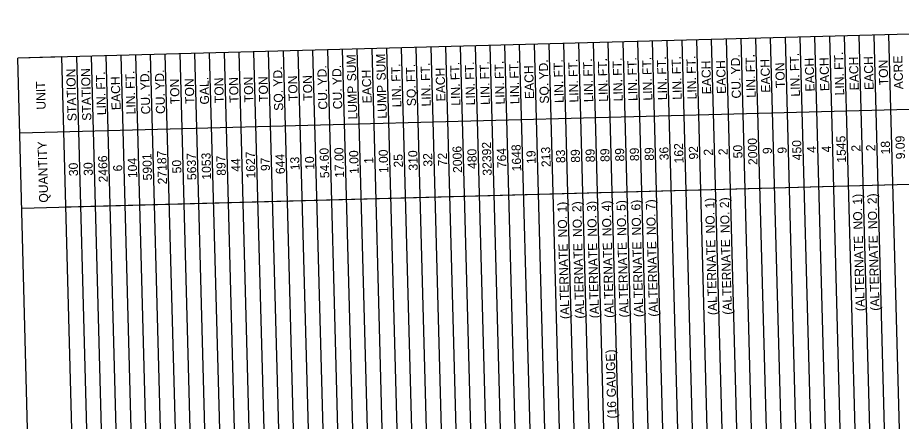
# Model space of a CAD drawing. Extents: x 1930091 to 1931962, y 596452 to 607874.
# Drawn here: x 1930094 to 1930677, y 606818 to 607084 of the extents above; entities that cross this region are included whole.
import ezdxf

# ---------------------------------------------------------------- set-up
doc = ezdxf.new("R2010")
doc.units = 0
doc.layers.add('Default', color=7, linetype='Continuous')

msp = doc.modelspace()

# ---------------------------------------------------------------- linework, layer by layer
at = {"layer": 'Default'}
for p, q in [((1931087.72, 607084.44), (1930093.58, 607057.76)), ((1930481.91, 606398.6), (1930463.95, 607067.7)), ((1930491.66, 606398.86), (1930473.69, 607067.96)), ((1930501.4, 606399.13), (1930483.44, 607068.22)), ((1930511.15, 606399.39), (1930493.19, 607068.48)), ((1930520.9, 606399.65), (1930502.93, 607068.75)), ((1930530.64, 606399.91), (1930512.68, 607069.01)), ((1930540.39, 606400.17), (1930522.43, 607069.27)), ((1930550.14, 606400.43), (1930532.17, 607069.53)), ((1930559.88, 606400.7), (1930541.92, 607069.79)), ((1930569.63, 606400.96), (1930551.67, 607070.05)), ((1930579.37, 606401.22), (1930561.41, 607070.32)), ((1930589.12, 606401.48), (1930571.16, 607070.58)), ((1930598.87, 606401.74), (1930580.91, 607070.84)), ((1930608.61, 606402), (1930590.65, 607071.1)), ((1930618.36, 606402.27), (1930600.4, 607071.36)), ((1930628.11, 606402.53), (1930610.15, 607071.62)), ((1930637.85, 606402.79), (1930619.89, 607071.89)), ((1930647.6, 606403.05), (1930629.64, 607072.15)), ((1930657.35, 606403.31), (1930639.39, 607072.41)), ((1930667.09, 606403.57), (1930649.13, 607072.67)), ((1930676.84, 606403.84), (1930658.88, 607072.93)), ((1930686.59, 606404.1), (1930668.62, 607073.19)), ((1930267.49, 606392.85), (1930249.53, 607061.94)), ((1930277.23, 606393.11), (1930259.27, 607062.21)), ((1930286.98, 606393.37), (1930269.02, 607062.47)), ((1930296.73, 606393.63), (1930278.77, 607062.73)), ((1930306.47, 606393.89), (1930288.51, 607062.99)), ((1930316.22, 606394.16), (1930298.26, 607063.25)), ((1930325.97, 606394.42), (1930308, 607063.51)), ((1930335.71, 606394.68), (1930317.75, 607063.78)), ((1930345.46, 606394.94), (1930327.5, 607064.04)), ((1930355.21, 606395.2), (1930337.24, 607064.3)), ((1930364.95, 606395.46), (1930346.99, 607064.56)), ((1930374.7, 606395.73), (1930356.74, 607064.82)), ((1930384.44, 606395.99), (1930366.48, 607065.08)), ((1930394.19, 606396.25), (1930376.23, 607065.34)), ((1930403.94, 606396.51), (1930385.98, 607065.61)), ((1930413.68, 606396.77), (1930395.72, 607065.87)), ((1930423.43, 606397.03), (1930405.47, 607066.13)), ((1930433.18, 606397.3), (1930415.22, 607066.39)), ((1930442.92, 606397.56), (1930424.96, 607066.65)), ((1930452.67, 606397.82), (1930434.71, 607066.91)), ((1930462.42, 606398.08), (1930444.46, 607067.18)), ((1930472.16, 606398.34), (1930454.2, 607067.44)), ((1930122.82, 607058.54), (1930093.58, 607057.76)), ((1930111.54, 606388.66), (1930093.58, 607057.76)), ((1930140.78, 606389.45), (1930122.82, 607058.54)), ((1930150.53, 606389.71), (1930132.57, 607058.8)), ((1930160.28, 606389.97), (1930142.31, 607059.07)), ((1930170.02, 606390.23), (1930152.06, 607059.33)), ((1930179.77, 606390.49), (1930161.81, 607059.59)), ((1930189.52, 606390.75), (1930171.55, 607059.85)), ((1930199.26, 606391.02), (1930181.3, 607060.11)), ((1930209.01, 606391.28), (1930191.05, 607060.37)), ((1930218.75, 606391.54), (1930200.79, 607060.64)), ((1930228.5, 606391.8), (1930210.54, 607060.9)), ((1930238.25, 606392.06), (1930220.29, 607061.16)), ((1930247.99, 606392.32), (1930230.03, 607061.42)), ((1930257.74, 606392.59), (1930239.78, 607061.68)), ((1931089.06, 607034.74), (1930094.92, 607008.05)), ((1930923.37, 607030.29), (1930094.92, 607008.05)), ((1931090.39, 606985.03), (1930096.25, 606958.34)), ((1930924.7, 606980.58), (1930125.49, 606959.13))]:
    msp.add_line(p, q, dxfattribs=at)

# ---------------------------------------------------------------- texts
for s, p in [(' SUM', (1930317.18, 607040.19)), (' SUM', (1930336.68, 607040.71)), (' YD.', (1930443.95, 607041.36)), (' FT.', (1930453.66, 607042.79)), (' FT.', (1930463.41, 607043.05)), (' FT.', (1930473.16, 607043.31)), (' FT.', (1930482.9, 607043.57)), (' FT.', (1930492.65, 607043.83)), (' FT.', (1930502.4, 607044.1)), (' FT.', (1930512.14, 607044.36)), (' FT.', (1930521.89, 607044.62)), (' FT.', (1930531.64, 607044.88)), (' FT.', (1930541.38, 607045.14)), (' YD.', (1930570.65, 607044.76)), (' FT.', (1930580.37, 607046.19)), ('EACH', (1930590.42, 607034.91)), (' FT.', (1930609.61, 607046.97)), ('EACH', (1930619.66, 607035.69)), ('EACH', (1930629.41, 607035.96)), (' FT.', (1930638.85, 607047.76)), ('EACH', (1930648.9, 607036.48)), ('EACH', (1930658.65, 607036.74)), ('TON', (1930668.32, 607039.81)), ('ACRE', (1930678.15, 607037.15)), ('STATION', (1930132.51, 607016.1)), ('STATION', (1930142.26, 607016.36)), (' YD.', (1930268.51, 607036.65)), (' YD.', (1930297.75, 607037.43)), (' YD.', (1930307.5, 607037.7)), (' FT.', (1930346.45, 607039.91)), (' FT.', (1930356.21, 607039.71)), (' FT.', (1930365.94, 607040.43)), ('EACH', (1930376, 607029.15)), (' FT.', (1930385.44, 607040.96)), (' FT.', (1930395.18, 607041.22)), (' FT.', (1930404.93, 607041.48)), (' FT.', (1930414.68, 607041.74)), (' FT.', (1930424.42, 607042)), ('EACH', (1930434.48, 607030.72)), ('EACH', (1930551.44, 607033.86)), ('EACH', (1930561.18, 607034.12)), ('TON', (1930600.1, 607037.97)), (' FT.', (1930151.52, 607034.68)), ('EACH', (1930161.58, 607023.4)), (' FT.', (1930171.02, 607035.2)), (' YD.', (1930180.79, 607034.29)), (' YD.', (1930190.54, 607034.56)), ('GAL.', (1930220, 607027.09)), ('TON', (1930229.73, 607028.03)), ('TON', (1930239.48, 607028.29)), ('TON', (1930249.22, 607028.55)), ('TON', (1930258.97, 607028.82)), ('TON', (1930278.46, 607029.34)), ('TON', (1930288.21, 607029.6)), ('EACH', (1930327.27, 607027.85)), ('LIN.', (1930541.77, 607030.51)), ('LIN.', (1930580.76, 607031.56)), ('LIN.', (1930610, 607032.34)), ('LIN.', (1930639.24, 607033.13)), ('UNIT', (1930112.13, 607023.69)), ('TON', (1930200.49, 607027.25)), ('TON', (1930210.24, 607027.51)), ('LUMP', (1930317.8, 607017.27)), ('LUMP', (1930337.29, 607017.79)), ('LIN.', (1930346.84, 607025.28)), ('SQ.', (1930356.58, 607026)), ('LIN.', (1930366.34, 607025.8)), ('LIN.', (1930385.83, 607026.32)), ('LIN.', (1930395.58, 607026.58)), ('LIN.', (1930405.32, 607026.85)), ('LIN.', (1930415.07, 607027.11)), ('LIN.', (1930424.82, 607027.37)), ('SQ.', (1930444.32, 607027.65)), ('LIN.', (1930454.06, 607028.15)), ('LIN.', (1930463.8, 607028.42)), ('LIN.', (1930473.55, 607028.68)), ('LIN.', (1930483.3, 607028.94)), ('LIN.', (1930493.04, 607029.2)), ('LIN.', (1930502.79, 607029.46)), ('LIN.', (1930512.54, 607029.72)), ('LIN.', (1930522.28, 607029.99)), ('LIN.', (1930532.03, 607030.25)), ('CU.', (1930571.02, 607031.06)), ('LIN.', (1930151.91, 607020.04)), ('LIN.', (1930171.41, 607020.57)), ('CU.', (1930181.16, 607020.59)), ('CU.', (1930190.91, 607020.85)), ('SQ.', (1930268.88, 607022.95)), ('CU.', (1930298.12, 607023.73)), ('CU.', (1930307.87, 607023.99)), ('2000', (1930581.95, 606987.13)), ('1545', (1930640.43, 606988.67)), ('9.09', (1930679.39, 606990.9)), ('QUANTITY', (1930113.78, 606962.25)), ('54.60', (1930299.34, 606978.38)), ('17.00', (1930309.08, 606978.64)), ('2006', (1930387.02, 606981.89)), ('32392', (1930406.58, 606980.11)), ('764', (1930416.2, 606985.01)), ('1648', (1930426.01, 606982.93)), ('213', (1930445.44, 606985.79)), ('89', (1930484.36, 606989.16)), ('89', (1930494.11, 606989.42)), ('89', (1930503.86, 606989.68)), ('89', (1930513.6, 606989.94)), ('36', (1930523.35, 606990.21)), ('162', (1930533.16, 606988.17)), ('92', (1930542.84, 606990.76)), ('2', (1930562.27, 606993.62)), ('50', (1930572.08, 606991.53)), ('9', (1930591.51, 606994.36)), ('9', (1930601.26, 606994.63)), ('450', (1930611.13, 606990.24)), ('4', (1930620.75, 606995.17)), ('4', (1930630.5, 606995.43)), ('2', (1930649.99, 606995.97)), ('2', (1930659.74, 606996.23)), ('18', (1930669.55, 606994.13)), ('2466', (1930153.11, 606975.61)), ('5901', (1930182.33, 606976.97)), ('27187', (1930192.16, 606974.32)), ('5637', (1930211.59, 606977.18)), ('1053', (1930221.33, 606977.44)), ('897', (1930231.02, 606980.03)), ('1627', (1930250.57, 606978.22)), ('644', (1930270, 606981.09)), ('13', (1930279.69, 606983.67)), ('10', (1930289.43, 606983.94)), ('1.00', (1930318.77, 606981.23)), ('1', (1930328.34, 606987.89)), ('1.00', (1930338.26, 606981.76)), ('25', (1930347.91, 606985.48)), ('310', (1930357.72, 606983.44)), ('32', (1930367.4, 606986.05)), ('72', (1930377.15, 606986.32)), ('480', (1930396.71, 606984.49)), ('19', (1930435.63, 606987.85)), ('83', (1930455.12, 606988.38)), ('89', (1930464.87, 606988.63)), ('89', (1930474.62, 606988.9)), ('2', (1930552.53, 606993.35)), ('30', (1930133.49, 606979.75)), ('30', (1930143.24, 606980.02)), ('6', (1930162.67, 606982.86)), ('104', (1930172.54, 606978.47)), ('50', (1930201.71, 606981.59)), ('44', (1930240.7, 606982.63)), ('97', (1930260.19, 606983.14)), (' 3)', (1930475.55, 606954.02)), (' 4)', (1930485.3, 606954.28)), (' 5)', (1930495.05, 606954.54)), (' 6)', (1930504.79, 606954.81)), (' 7)', (1930514.54, 606955.07)), (' 1)', (1930553.53, 606956.11)), (' 2)', (1930563.27, 606956.38)), (' 1)', (1930650.99, 606958.73)), (' 2)', (1930660.74, 606958.99)), (' 1)', (1930456.06, 606953.5)), (' 2)', (1930465.81, 606953.76)), (' NO.', (1930651.43, 606942.24)), (' NO.', (1930661.18, 606942.5)), (' NO.', (1930456.5, 606937)), (' NO.', (1930466.25, 606937.27)), (' NO.', (1930476, 606937.53)), (' NO.', (1930485.74, 606937.79)), (' NO.', (1930495.49, 606938.05)), (' NO.', (1930505.24, 606938.31)), (' NO.', (1930514.98, 606938.57)), (' NO.', (1930553.97, 606939.62)), (' NO.', (1930563.71, 606939.88)), ('(ALTERNATE', (1930652.82, 606890.53)), ('(ALTERNATE', (1930662.57, 606890.79)), ('(ALTERNATE', (1930457.89, 606885.3)), ('(ALTERNATE', (1930467.64, 606885.56)), ('(ALTERNATE', (1930477.38, 606885.82)), ('(ALTERNATE', (1930487.13, 606886.08)), ('(ALTERNATE', (1930496.88, 606886.34)), ('(ALTERNATE', (1930506.62, 606886.6)), ('(ALTERNATE', (1930516.37, 606886.86)), ('(ALTERNATE', (1930555.36, 606887.91)), ('(ALTERNATE', (1930565.1, 606888.17)), (' GAUGE)', (1930488.6, 606831.34)), (' (16', (1930488.98, 606817.28))]:
    msp.add_text(s, height=6, rotation=91.53769, dxfattribs=at).set_placement(p)

doc.saveas('drawing.dxf')
